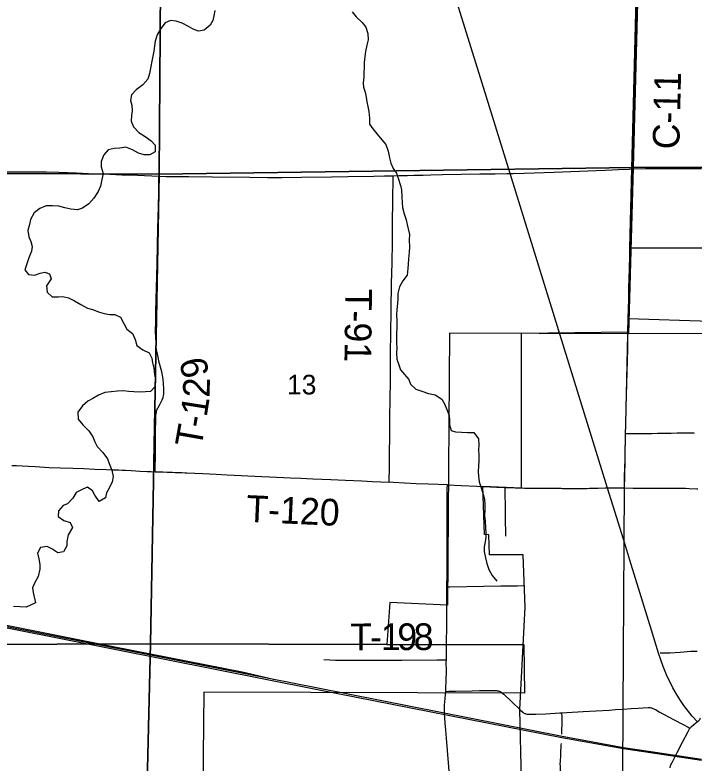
# Model space of a CAD drawing. Extents: x 0 to 34, y 0 to 22.
# Drawn here: x 3.064 to 3.787, y 16.12 to 16.916 of the extents above; entities that cross this region are included whole.
import ezdxf

# ---------------------------------------------------------------- set-up
doc = ezdxf.new("R2010")
doc.units = 0
for name, color, linetype in [('GM_X_City_Street', 7, 'Continuous'), ('GM_X_Corporation', 7, 'Continuous'), ('GM_X_County_Road', 7, 'Continuous'), ('GM_X_County_Road_Text', 7, 'Continuous'), ('GM_X_Minor_River', 7, 'Continuous'), ('GM_X_Rail_Line', 7, 'Continuous'), ('GM_X_Section_Text', 7, 'Continuous'), ('GM_X_Township_Road', 7, 'Continuous'), ('GM_X_Township_Road_Text', 7, 'Continuous')]:
    doc.layers.add(name, color=color, linetype=linetype)

msp = doc.modelspace()

# ---------------------------------------------------------------- linework, layer by layer
at = {"layer": 'GM_X_City_Street'}
for points in [[(3.71381, 16.47026), (3.71554, 16.47028), (3.7259, 16.4704), (3.74161, 16.47053), (3.7477, 16.4706), (3.75779, 16.47071), (3.76224, 16.47084), (3.76846, 16.47105), (3.77184, 16.47114), (3.7735, 16.47119), (3.77767, 16.4712), (3.78017, 16.47123), (3.78203, 16.47122), (3.78513, 16.47116), (3.78563, 16.47111), (3.78611, 16.47104), (3.78662, 16.47092)], [(3.58625, 16.36101), (3.58618, 16.36576), (3.58593, 16.37698), (3.58585, 16.38788), (3.58565, 16.41189), (3.58564, 16.41303)], [(3.71269, 16.41246), (3.72194, 16.4124), (3.74855, 16.4121), (3.76285, 16.41211), (3.77748, 16.41209), (3.78152, 16.41193), (3.78958, 16.41143), (3.79058, 16.41141)], [(3.75054, 16.23699), (3.76135, 16.23715), (3.77176, 16.23781), (3.7832, 16.23862), (3.78978, 16.23888)], [(3.646, 16.17313), (3.65105, 16.17339), (3.66871, 16.17441), (3.69622, 16.17613), (3.70304, 16.17658), (3.71143, 16.17716), (3.71981, 16.17773), (3.72726, 16.17823), (3.73253, 16.1786), (3.73782, 16.17891), (3.73893, 16.17886), (3.73969, 16.17879), (3.74055, 16.17863), (3.74129, 16.17842), (3.74211, 16.17813), (3.74273, 16.17786), (3.74543, 16.17654), (3.7495, 16.17426), (3.76457, 16.16615), (3.77504, 16.16065), (3.78038, 16.15774), (3.7822, 16.15675)], [(3.64581, 16.15029), (3.64635, 16.16586), (3.64633, 16.16717), (3.64627, 16.1686), (3.646, 16.17313)], [(3.7822, 16.15675), (3.78266, 16.15737), (3.78306, 16.15782), (3.78354, 16.15829), (3.78646, 16.1608), (3.79184, 16.16514), (3.79244, 16.1658), (3.79276, 16.16622), (3.79313, 16.16686), (3.79327, 16.16718), (3.79348, 16.16785)], [(3.76116, 16.11463), (3.7617, 16.11681), (3.76223, 16.11836), (3.76278, 16.11964), (3.7642, 16.12252), (3.76862, 16.13108), (3.77425, 16.1418), (3.78027, 16.1534), (3.78102, 16.15484), (3.7814, 16.15551), (3.78182, 16.1562), (3.7822, 16.15675)], [(3.64988, 16.09), (3.6489, 16.09331), (3.64822, 16.09563), (3.64779, 16.09708), (3.64755, 16.09795), (3.64699, 16.10002), (3.6458, 16.10484), (3.64503, 16.10881), (3.6446, 16.1122), (3.64431, 16.11623), (3.64425, 16.11902), (3.64432, 16.12148), (3.6447, 16.12766), (3.64499, 16.13261), (3.64511, 16.13602), (3.6453, 16.13912), (3.64541, 16.14036)]]:
    msp.add_lwpolyline(points, dxfattribs=at)
at = {"layer": 'GM_X_Corporation'}
for points in [[(3.22087, 17.24589), (3.73479, 17.25336), (3.72171, 16.75343), (3.21747, 16.74646)], [(3.73479, 17.25336), (4.27027, 17.25592), (4.26039, 16.75407), (3.72171, 16.75343)], [(2.71917, 17.24799), (3.22087, 17.24589), (3.21747, 16.74646), (2.71424, 16.74839)], [(3.72171, 16.75343), (3.71695, 16.57631), (3.52635, 16.57719), (3.52434, 16.28788), (3.46272, 16.29045), (3.45984, 16.24604), (3.20823, 16.24661), (3.21747, 16.74646)], [(4.26039, 16.75407), (4.25771, 16.57674), (3.71695, 16.57631), (3.72171, 16.75343)], [(3.21747, 16.74646), (3.20823, 16.24661), (2.71086, 16.24467), (2.71424, 16.74839)], [(2.71086, 16.24467), (3.20823, 16.24661), (3.19629, 15.74328), (2.70763, 15.74147)], [(3.20823, 16.24661), (3.45984, 16.24604), (3.60555, 16.2457), (3.6061, 16.19397), (3.26506, 16.19502), (3.26092, 15.8218), (3.70451, 15.82679), (3.70316, 15.74798), (3.19629, 15.74328)]]:
    msp.add_lwpolyline(points, close=True, dxfattribs=at)
for points in [[(3.84752, 16.66766), (3.7183, 16.66747), (3.72042, 16.75218), (3.72688, 17.00193)], [(3.71095, 16.10763), (3.71132, 16.17743), (3.71258, 16.41273), (3.71273, 16.42477), (3.71312, 16.44309), (3.71333, 16.45367), (3.71349, 16.46173), (3.7137, 16.47053), (3.7139, 16.47917), (3.71433, 16.49838), (3.71471, 16.51141), (3.71585, 16.56071), (3.71618, 16.57518), (3.71621, 16.57851), (3.71657, 16.59213), (3.71658, 16.59262), (3.71706, 16.6131), (3.71734, 16.62593), (3.7175, 16.63473), (3.71775, 16.64622), (3.71811, 16.65927), (3.7183, 16.66747), (3.71855, 16.67823), (3.71925, 16.70713), (3.71963, 16.72017), (3.72012, 16.7385), (3.72042, 16.75218), (3.72081, 16.76647), (3.7212, 16.77919), (3.72133, 16.78297), (3.72155, 16.79131), (3.72238, 16.82302), (3.7243, 16.89543), (3.72475, 16.91065), (3.72515, 16.92685)], [(3.71095, 16.10763), (3.71132, 16.17743), (3.71258, 16.41273), (3.71273, 16.42477), (3.71312, 16.44309), (3.71333, 16.45367), (3.71349, 16.46173), (3.7137, 16.47053), (3.7139, 16.47917), (3.71433, 16.49838), (3.71471, 16.51141), (3.71585, 16.56071), (3.71618, 16.57518), (3.71621, 16.57851), (3.71657, 16.59213), (3.71658, 16.59262), (3.71706, 16.6131), (3.71734, 16.62593), (3.7175, 16.63473), (3.71775, 16.64622), (3.71811, 16.65927), (3.7183, 16.66747), (3.71855, 16.67823), (3.71925, 16.70713), (3.71963, 16.72017), (3.72012, 16.7385), (3.72042, 16.75218), (3.72081, 16.76647), (3.7212, 16.77919), (3.72133, 16.78297), (3.72155, 16.79131), (3.72238, 16.82302), (3.7243, 16.89543), (3.72475, 16.91065), (3.72515, 16.92685)], [(3.60307, 16.10143), (3.60137, 16.17661), (3.60687, 16.28561), (3.60467, 16.34115), (3.56881, 16.34113), (3.56816, 16.36254), (3.56378, 16.3628), (3.56183, 16.41431), (3.60313, 16.41272), (3.60303, 16.57728), (3.71621, 16.57851), (3.71658, 16.59262), (3.80418, 16.58998)]]:
    msp.add_lwpolyline(points, dxfattribs=at)
at = {"layer": 'GM_X_County_Road'}
for points in [[(3.72053, 16.75191), (3.72092, 16.76619), (3.72132, 16.77891), (3.72144, 16.78269), (3.72166, 16.79104), (3.7225, 16.82274), (3.72441, 16.89516), (3.72486, 16.91037), (3.72526, 16.92658), (3.72612, 16.95544), (3.72657, 16.97464), (3.72706, 16.99142), (3.72722, 16.99928), (3.7282, 17.03279), (3.7283, 17.03658)], [(3.00317, 16.74907), (3.02626, 16.74901), (3.04024, 16.7489), (3.05268, 16.74898), (3.08436, 16.74894), (3.09772, 16.74882), (3.11084, 16.74849), (3.12951, 16.74772), (3.14214, 16.74719), (3.15858, 16.74657), (3.17766, 16.74584), (3.19424, 16.74514), (3.2172, 16.74427)], [(3.46659, 16.74472), (3.47243, 16.74482), (3.48175, 16.745), (3.48895, 16.74527), (3.49821, 16.74542), (3.5066, 16.74559), (3.51884, 16.74585), (3.5585, 16.74657), (3.57497, 16.74683), (3.58776, 16.74708), (3.59144, 16.74715), (3.59415, 16.74723), (3.60572, 16.74756), (3.63772, 16.74848), (3.68244, 16.7503), (3.69238, 16.75076), (3.70573, 16.75136), (3.71754, 16.75178), (3.72053, 16.75191)], [(3.71841, 16.66719), (3.71867, 16.67795), (3.71936, 16.70685), (3.71974, 16.7199), (3.72023, 16.73823), (3.72053, 16.75191)], [(3.2172, 16.74427), (3.22506, 16.74404), (3.2384, 16.7438), (3.24905, 16.74372), (3.27422, 16.74348), (3.31393, 16.74303), (3.33285, 16.7428), (3.34794, 16.7428), (3.36894, 16.74317), (3.40095, 16.74366), (3.41835, 16.74396), (3.4457, 16.74434), (3.4572, 16.74456), (3.46659, 16.74472)], [(3.71669, 16.59234), (3.71717, 16.61282), (3.71745, 16.62566), (3.71761, 16.63445), (3.71786, 16.64595), (3.71822, 16.65899), (3.71841, 16.66719)], [(3.71633, 16.57824), (3.71668, 16.59185), (3.71669, 16.59234)], [(3.71381, 16.47026), (3.71401, 16.47889), (3.71444, 16.4981), (3.71483, 16.51113), (3.71596, 16.56043), (3.71629, 16.57491), (3.71633, 16.57824)], [(3.71269, 16.41246), (3.71284, 16.4245), (3.71323, 16.44282), (3.71344, 16.4534), (3.7136, 16.46146), (3.71381, 16.47026)]]:
    msp.add_lwpolyline(points, dxfattribs=at)
at = {"layer": 'GM_X_Minor_River'}
for points in [[(3.27678, 16.92042), (3.27561, 16.91492), (3.27444, 16.90999), (3.27176, 16.90507), (3.26548, 16.89979), (3.25941, 16.89869), (3.25355, 16.90081), (3.24865, 16.90369), (3.24204, 16.90715), (3.23561, 16.90927), (3.22937, 16.90988), (3.22367, 16.90725), (3.21927, 16.90121), (3.21545, 16.89458), (3.21332, 16.88795), (3.21253, 16.88302), (3.21174, 16.87714), (3.20978, 16.86652), (3.20861, 16.86102), (3.20724, 16.85363), (3.2053, 16.84737), (3.19996, 16.84152), (3.19311, 16.83625), (3.18816, 16.83077), (3.18698, 16.8247), (3.18847, 16.81976), (3.18881, 16.81368)], [(3.4228, 16.91899), (3.42712, 16.91364), (3.43334, 16.90772), (3.43728, 16.90276), (3.43951, 16.89592), (3.43985, 16.88946), (3.4383, 16.88358), (3.43693, 16.87676), (3.43633, 16.87164), (3.43572, 16.86519), (3.4355, 16.85987), (3.43528, 16.85494), (3.43506, 16.84962), (3.43464, 16.84355), (3.4348, 16.8388), (3.43647, 16.83348), (3.43777, 16.82835), (3.43849, 16.82341), (3.43941, 16.81827), (3.4407, 16.81295), (3.44123, 16.80592), (3.44138, 16.79966), (3.44494, 16.7947), (3.44927, 16.78898), (3.45453, 16.78287), (3.45848, 16.77811), (3.46109, 16.77088), (3.46256, 16.76384), (3.46404, 16.75814), (3.46646, 16.75243), (3.46984, 16.74728), (3.47189, 16.74196), (3.47431, 16.73435), (3.47541, 16.7296), (3.47575, 16.72219), (3.47589, 16.71573), (3.47643, 16.71098), (3.4781, 16.70414), (3.48014, 16.69767), (3.48125, 16.69292), (3.48254, 16.68817), (3.48383, 16.68228), (3.48361, 16.67639), (3.48375, 16.6688), (3.48334, 16.66348), (3.48272, 16.65627), (3.4825, 16.65077), (3.48209, 16.64603), (3.48129, 16.63882), (3.47671, 16.63277), (3.47326, 16.62634), (3.47132, 16.61932), (3.47129, 16.61401), (3.47088, 16.60889), (3.47046, 16.60224), (3.47004, 16.59655), (3.47038, 16.59009), (3.47033, 16.58231), (3.47011, 16.57757), (3.47004, 16.56637), (3.4702, 16.56162), (3.46998, 16.55612), (3.47032, 16.54966), (3.47236, 16.54338)], [(3.18881, 16.81368), (3.18802, 16.80894), (3.1876, 16.80268), (3.19003, 16.79659), (3.19586, 16.79086), (3.20265, 16.78645), (3.20887, 16.78186), (3.2132, 16.77709), (3.21335, 16.77006), (3.20746, 16.76687), (3.20159, 16.7669), (3.19554, 16.76884), (3.18893, 16.77229), (3.18213, 16.77499), (3.17568, 16.77408), (3.16943, 16.77355), (3.16317, 16.77226), (3.1584, 16.76678), (3.15571, 16.75977), (3.15567, 16.75407), (3.15771, 16.74704), (3.15635, 16.74078), (3.15498, 16.73377), (3.15248, 16.72809), (3.14808, 16.72071), (3.14274, 16.71485), (3.1357, 16.71034), (3.13039, 16.70847), (3.12339, 16.70927), (3.11695, 16.71064), (3.11053, 16.71239), (3.1039, 16.71261), (3.09708, 16.71284), (3.09043, 16.70985), (3.08453, 16.70532), (3.08051, 16.69813), (3.07953, 16.69282), (3.0776, 16.68638), (3.07888, 16.67973), (3.08075, 16.67459), (3.08242, 16.66927), (3.08144, 16.66434), (3.07894, 16.65752), (3.07682, 16.65202), (3.0745, 16.64463), (3.07826, 16.63968), (3.08488, 16.63907), (3.09077, 16.64093), (3.0957, 16.64204), (3.1008, 16.6403), (3.10247, 16.63517), (3.09769, 16.62741), (3.09841, 16.62095), (3.10349, 16.61599), (3.11031, 16.61576), (3.11504, 16.61611), (3.12091, 16.61475), (3.12752, 16.61148), (3.13393, 16.60765), (3.14129, 16.60381), (3.14659, 16.60226), (3.15396, 16.59956), (3.15887, 16.59801), (3.16493, 16.59721), (3.17023, 16.59699), (3.17627, 16.59411), (3.1802, 16.58687), (3.18301, 16.58135), (3.18923, 16.57695), (3.19203, 16.57048), (3.1937, 16.56401), (3.20011, 16.55961), (3.20691, 16.55634), (3.20953, 16.55044), (3.21044, 16.5455), (3.21192, 16.5398), (3.21264, 16.53315), (3.21355, 16.52745), (3.21313, 16.52043), (3.20836, 16.51514), (3.20286, 16.5146), (3.19661, 16.51445), (3.19037, 16.51486), (3.18525, 16.51508), (3.17901, 16.51569), (3.17295, 16.51554), (3.1665, 16.51463), (3.15949, 16.51391), (3.15303, 16.51129), (3.14695, 16.50772), (3.14163, 16.5049), (3.13592, 16.5), (3.13095, 16.493), (3.13128, 16.4856), (3.13617, 16.47968), (3.14257, 16.47319), (3.14669, 16.46671), (3.14912, 16.46138), (3.15156, 16.45662), (3.15739, 16.45032), (3.16246, 16.44346)], [(3.47236, 16.54338), (3.47423, 16.53825), (3.47836, 16.53329), (3.48325, 16.52775), (3.48493, 16.523), (3.49039, 16.51765), (3.49681, 16.51552), (3.50418, 16.51301), (3.51099, 16.51145), (3.51816, 16.50685), (3.52097, 16.50209), (3.52359, 16.496), (3.52601, 16.48953), (3.52635, 16.48421), (3.52651, 16.47946), (3.52799, 16.47357), (3.53291, 16.47202), (3.53916, 16.47179), (3.54559, 16.47138), (3.55222, 16.47134), (3.55711, 16.46485), (3.55744, 16.45821), (3.55741, 16.45251), (3.55757, 16.44777), (3.55772, 16.44169), (3.5573, 16.43562), (3.55689, 16.43011), (3.55724, 16.42518), (3.55796, 16.41891), (3.56019, 16.41244), (3.56223, 16.4054), (3.56371, 16.40046), (3.56406, 16.39476), (3.56402, 16.38888), (3.56379, 16.38299), (3.56433, 16.3771), (3.56466, 16.36989), (3.56501, 16.36476), (3.56498, 16.36002), (3.56438, 16.35508), (3.5634, 16.34996), (3.56337, 16.34484), (3.56465, 16.33819), (3.56613, 16.3321), (3.56818, 16.32583), (3.57192, 16.31935), (3.57662, 16.31344)], [(3.16246, 16.44346), (3.16413, 16.43851), (3.16693, 16.43147), (3.16859, 16.42482), (3.16742, 16.41894), (3.16416, 16.41231), (3.16129, 16.40721), (3.16031, 16.40209), (3.15347, 16.39814), (3.14896, 16.40462), (3.14653, 16.40938), (3.14106, 16.41321), (3.13631, 16.41115), (3.12928, 16.40777), (3.12546, 16.40172), (3.11993, 16.39549), (3.11518, 16.39362), (3.11022, 16.38814), (3.11, 16.38207), (3.11584, 16.37786), (3.12283, 16.37554), (3.12508, 16.3704), (3.12067, 16.36245), (3.11911, 16.35563), (3.11908, 16.35088), (3.11564, 16.34464), (3.10957, 16.34353), (3.10334, 16.34756), (3.09824, 16.35006), (3.09123, 16.34915), (3.08797, 16.3429), (3.08926, 16.3372), (3.09036, 16.33093), (3.09052, 16.32618), (3.08877, 16.31822), (3.08493, 16.31103), (3.08263, 16.3061), (3.08336, 16.30116), (3.08571, 16.29032)], [(3.08571, 16.29032), (3.07576, 16.28564), (3.06931, 16.28588), (3.06229, 16.28631)]]:
    msp.add_lwpolyline(points, dxfattribs=at)
at = {"layer": 'GM_X_Rail_Line'}
for points in [[(3.79012, 16.16346), (3.78472, 16.16964), (3.77578, 16.18107), (3.7722, 16.18637), (3.77033, 16.18923), (3.76752, 16.19375), (3.76414, 16.19967), (3.76144, 16.20492), (3.75812, 16.21178), (3.7537, 16.22233), (3.74882, 16.23682), (3.74133, 16.26119), (3.72892, 16.3011), (3.71842, 16.33555), (3.71281, 16.35352), (3.70434, 16.38075), (3.69457, 16.41239), (3.59084, 16.74699), (3.56099, 16.84313), (3.51241, 16.99979)], [(2.73876, 16.32795), (2.75401, 16.32619), (3.00844, 16.27565), (3.1684, 16.24389), (3.3058, 16.21685), (3.3391, 16.20895)], [(3.00714, 16.27321), (3.38603, 16.19798), (3.64601, 16.14695), (3.71143, 16.13519), (3.74028, 16.13094), (3.79436, 16.12262)], [(3.0082, 16.27443), (3.38623, 16.19962), (3.64624, 16.14817), (3.71164, 16.13642), (3.74046, 16.13217), (3.79455, 16.12385)]]:
    msp.add_lwpolyline(points, dxfattribs=at)
at = {"layer": 'GM_X_Township_Road'}
for points in [[(3.00317, 16.74907), (3.02626, 16.74901), (3.04024, 16.7489), (3.05268, 16.74898), (3.08436, 16.74894), (3.09772, 16.74882), (3.11084, 16.74849), (3.12951, 16.74772), (3.14214, 16.74719), (3.15858, 16.74657), (3.17766, 16.74584), (3.19424, 16.74514), (3.2172, 16.74427)], [(3.46659, 16.74472), (3.47243, 16.74482), (3.48175, 16.745), (3.48895, 16.74527), (3.49821, 16.74542), (3.5066, 16.74559), (3.51884, 16.74585), (3.5585, 16.74657), (3.57497, 16.74683), (3.58776, 16.74708), (3.59144, 16.74715), (3.59415, 16.74723), (3.60572, 16.74756), (3.63772, 16.74848), (3.68244, 16.7503), (3.69238, 16.75076), (3.70573, 16.75136), (3.71754, 16.75178), (3.72053, 16.75191)], [(3.72053, 16.75191), (3.73478, 16.75227), (3.75595, 16.75225), (3.77273, 16.75232), (3.78236, 16.75236), (3.79456, 16.75244)], [(3.21312, 16.42979), (3.21317, 16.43312), (3.21339, 16.44711), (3.21364, 16.46016), (3.2137, 16.47352), (3.21381, 16.48409), (3.21395, 16.48905), (3.21415, 16.49126), (3.21444, 16.4929), (3.21472, 16.49442), (3.21509, 16.4957), (3.21555, 16.49673), (3.21624, 16.49796), (3.21789, 16.50068), (3.21937, 16.50331), (3.22068, 16.50614), (3.22154, 16.50861), (3.22212, 16.51075), (3.22237, 16.51244), (3.22245, 16.51486), (3.22241, 16.51819), (3.22216, 16.52337), (3.22162, 16.52835), (3.22104, 16.53213), (3.22014, 16.53612), (3.21713, 16.54751), (3.21664, 16.54973), (3.21623, 16.55175), (3.21528, 16.55656), (3.21475, 16.55952), (3.21441, 16.56256), (3.21413, 16.56684), (3.21386, 16.57241), (3.21371, 16.57893), (3.21379, 16.59011), (3.21394, 16.60006), (3.21527, 16.6507), (3.2156, 16.67121), (3.21602, 16.6883), (3.2166, 16.71191), (3.21717, 16.72762), (3.21725, 16.73119), (3.21712, 16.73568), (3.21716, 16.74143), (3.2172, 16.74427)], [(3.2172, 16.74427), (3.22506, 16.74404), (3.2384, 16.7438), (3.24905, 16.74372), (3.27422, 16.74348), (3.31393, 16.74303), (3.33285, 16.7428), (3.34794, 16.7428), (3.36894, 16.74317), (3.40095, 16.74366), (3.41835, 16.74396), (3.4457, 16.74434), (3.4572, 16.74456), (3.46659, 16.74472)], [(3.46231, 16.41857), (3.46239, 16.43539), (3.46263, 16.45023), (3.46283, 16.46676), (3.46295, 16.48822), (3.46319, 16.50661), (3.46343, 16.52671), (3.46366, 16.53982), (3.46367, 16.55568), (3.46381, 16.57744), (3.46416, 16.60107), (3.46476, 16.63116), (3.46496, 16.63983), (3.46525, 16.65295), (3.46561, 16.67288), (3.46589, 16.69522), (3.46618, 16.71772), (3.46658, 16.74375), (3.46659, 16.74472)], [(3.06057, 16.4365), (3.06551, 16.43625), (3.07172, 16.43592), (3.07826, 16.43556), (3.08533, 16.43515), (3.10026, 16.43437), (3.11239, 16.43384), (3.12547, 16.43335), (3.13718, 16.43302), (3.14898, 16.43256), (3.1614, 16.43201), (3.16761, 16.43183), (3.17071, 16.43175), (3.17415, 16.43164), (3.17813, 16.43148), (3.18154, 16.4313), (3.18773, 16.43096), (3.19269, 16.43064), (3.19672, 16.4304), (3.2048, 16.43), (3.20852, 16.42992), (3.21312, 16.42979)], [(3.21312, 16.42979), (3.21598, 16.42972), (3.21939, 16.4296), (3.22125, 16.42954), (3.2259, 16.42936), (3.2287, 16.42925), (3.2318, 16.42911), (3.23459, 16.429), (3.23832, 16.42886), (3.24173, 16.42876), (3.24514, 16.42864), (3.24701, 16.42855), (3.26395, 16.42774), (3.27804, 16.42706), (3.28983, 16.42643), (3.32677, 16.42466), (3.33485, 16.42435), (3.3572, 16.42339), (3.36806, 16.4229), (3.3811, 16.42234), (3.40003, 16.42147), (3.41587, 16.42076), (3.43293, 16.41989), (3.44442, 16.41938), (3.46231, 16.41857)], [(3.52408, 16.41571), (3.504, 16.41643), (3.49095, 16.41699), (3.47841, 16.41761), (3.46664, 16.41825), (3.46231, 16.41857)], [(3.52368, 16.30725), (3.52371, 16.31136), (3.52374, 16.31639), (3.52382, 16.32696), (3.52376, 16.34001), (3.52379, 16.35617), (3.52381, 16.35912), (3.52382, 16.3607), (3.52387, 16.36923), (3.52401, 16.3885), (3.52406, 16.40435), (3.52404, 16.41149), (3.52408, 16.41571)], [(3.52408, 16.41571), (3.53883, 16.41499), (3.55558, 16.41428), (3.56233, 16.41399)], [(3.56233, 16.41399), (3.57666, 16.41336), (3.58564, 16.41303)], [(3.58564, 16.41303), (3.5962, 16.41263), (3.60201, 16.41247), (3.60356, 16.41243)], [(3.60356, 16.41243), (3.60602, 16.41241), (3.61533, 16.41238), (3.62489, 16.41236), (3.62658, 16.41235), (3.62709, 16.41235), (3.62762, 16.41235), (3.62842, 16.41235), (3.62898, 16.41234), (3.63008, 16.41234), (3.63116, 16.41233), (3.63226, 16.41232), (3.63341, 16.4123), (3.63426, 16.41229), (3.63538, 16.41227), (3.63647, 16.41226), (3.63796, 16.41223), (3.63913, 16.4122), (3.64063, 16.41217), (3.64239, 16.41213), (3.64297, 16.41212), (3.64504, 16.41208), (3.64655, 16.41205), (3.64868, 16.41201), (3.64958, 16.412), (3.65107, 16.41198), (3.65441, 16.41197), (3.65709, 16.41198), (3.65786, 16.41197), (3.65867, 16.41197), (3.6592, 16.41196), (3.66031, 16.41197), (3.66201, 16.41197), (3.66286, 16.41198), (3.66432, 16.41198), (3.66787, 16.41198), (3.66937, 16.412), (3.67058, 16.41201), (3.67303, 16.41204), (3.6755, 16.4121), (3.67797, 16.41218), (3.68447, 16.41235), (3.69191, 16.41248), (3.71269, 16.41246)], [(3.52302, 16.22946), (3.52312, 16.23899), (3.52345, 16.2738), (3.52366, 16.30491), (3.52368, 16.30725)], [(3.52368, 16.30725), (3.52671, 16.30731), (3.56247, 16.30795), (3.58099, 16.30846), (3.59875, 16.30843), (3.6055, 16.30854)], [(3.39257, 16.23005), (3.39903, 16.22965), (3.4052, 16.2293), (3.40717, 16.22919), (3.41461, 16.2292), (3.43326, 16.22925), (3.4758, 16.2293), (3.51277, 16.22951), (3.52029, 16.22947), (3.52302, 16.22946)], [(3.52231, 16.19602), (3.52248, 16.19746), (3.52263, 16.19954), (3.52287, 16.20729), (3.52304, 16.21817), (3.52299, 16.22688), (3.52302, 16.22946)], [(3.52703, 16.09759), (3.52668, 16.10271), (3.52334, 16.14609), (3.52259, 16.15477), (3.52186, 16.1622), (3.52132, 16.16836), (3.52114, 16.17183), (3.52109, 16.17499), (3.52104, 16.17775), (3.52114, 16.18157), (3.52128, 16.18449), (3.5216, 16.18865), (3.52231, 16.19602)], [(3.52231, 16.19602), (3.52573, 16.19607), (3.53289, 16.19618), (3.5506, 16.19653), (3.55839, 16.19675), (3.56345, 16.19684), (3.57366, 16.197), (3.57594, 16.1969), (3.57681, 16.19682), (3.5774, 16.19672), (3.57805, 16.19658), (3.57881, 16.19636), (3.57944, 16.19612), (3.58029, 16.19571), (3.5809, 16.19534), (3.58184, 16.1947), (3.58247, 16.19423), (3.58405, 16.19292), (3.59263, 16.18478), (3.60148, 16.17634), (3.60447, 16.17389), (3.60525, 16.17328), (3.60585, 16.17289), (3.60637, 16.17261), (3.60689, 16.17237), (3.60752, 16.1721), (3.60866, 16.17182)], [(3.60866, 16.17182), (3.6091, 16.17176), (3.60989, 16.17169), (3.61079, 16.17165), (3.6115, 16.17166), (3.61295, 16.17166), (3.61527, 16.1717), (3.61815, 16.17167), (3.62886, 16.17223), (3.64377, 16.17303), (3.646, 16.17313)]]:
    msp.add_lwpolyline(points, dxfattribs=at)

# ---------------------------------------------------------------- texts
at = {"layer": 'GM_X_County_Road_Text'}
msp.add_text('C-11', height=0.028409, rotation=88.65243, dxfattribs=at).set_placement((3.77088, 16.77259))
at = {"layer": 'GM_X_Section_Text'}
msp.add_text('13', height=0.020928, rotation=0.00001, dxfattribs=at).set_placement((3.35361, 16.51196))
at = {"layer": 'GM_X_Township_Road_Text'}
for s, height, rotation, p in [('T-91', 0.028409, 269.29305, (3.41555, 16.62462)), ('9', 0.02841, 101.85915, (3.27082, 16.53314)), ('2', 0.02841, 88.56651, (3.27103, 16.50851)), ('1', 0.02841, 81.01808, (3.26793, 16.48716)), ('-', 0.02841, 80.19224, (3.26587, 16.47522)), ('T', 0.02841, 80.01138, (3.26217, 16.4542)), ('T-120', 0.028409, 357.39615, (3.30969, 16.37653)), ('T', 0.02841, 0.0932, (3.42073, 16.23979)), ('1', 0.02841, 0.1161, (3.45352, 16.23985)), ('9', 0.02841, 0.17187, (3.47091, 16.23988)), ('8', 0.02841, 0.21735, (3.4883, 16.23993)), ('-', 0.02841, 0.09405, (3.44194, 16.23983))]:
    msp.add_text(s, height=height, rotation=rotation, dxfattribs=at).set_placement(p)

doc.saveas('drawing.dxf')
